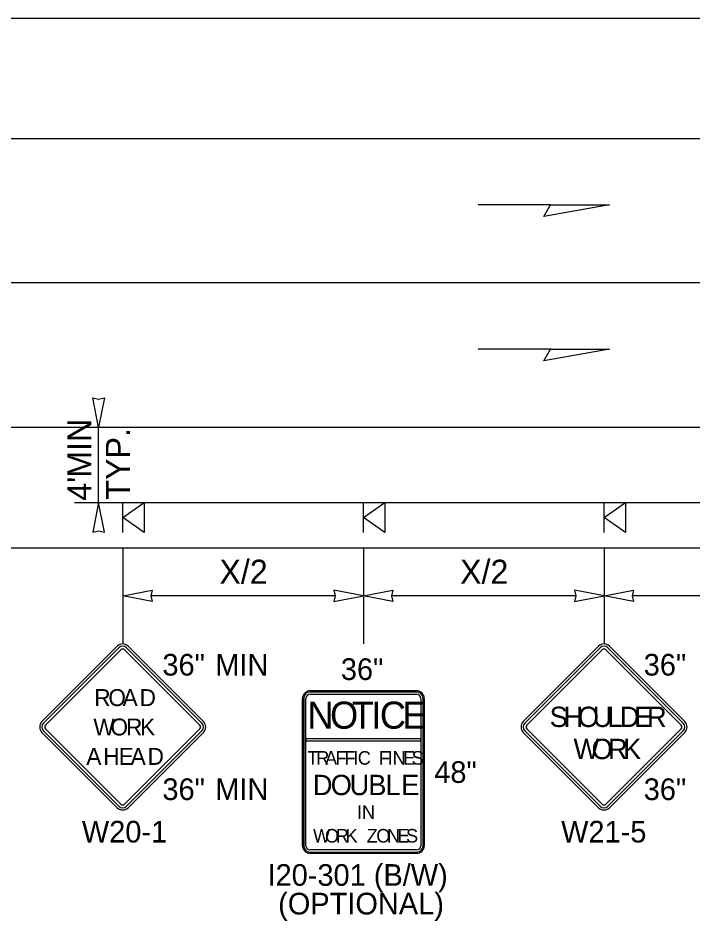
# Model space of a CAD drawing. Extents: x 99999.1 to 100055.7, y 99995 to 100010.7.
# Drawn here: x 100021.827 to 100024.071, y 100003.995 to 100006.996 of the extents above; entities that cross this region are included whole.
import ezdxf

# ---------------------------------------------------------------- set-up
doc = ezdxf.new("R2010")
doc.units = 0
for name, color, linetype in [('RD_ED_ShoulderPavedEdge', 7, 'Continuous'), ('RD_MK_LineEdgeWhite', 7, 'Continuous'), ('RD_MK_LineEdgeYellow', 7, 'Continuous'), ('RD_MK_LineLane', 7, 'Continuous'), ('TR_SN_ConstructionSigns', 7, 'Continuous'), ('TR_WZ_PortableSignMountBlk-Org', 7, 'Continuous'), ('TR_WZ_PortableSignMountBlk-Wht', 7, 'Continuous'), ('TR_WZ_WorkZoneDetails', 7, 'Continuous'), ('TR_WZ_WorkZoneTextCurrent', 7, 'Continuous')]:
    doc.layers.add(name, color=color, linetype=linetype)

msp = doc.modelspace()

# ---------------------------------------------------------------- linework, layer by layer
at = {"layer": 'RD_ED_ShoulderPavedEdge'}
for p, q in [((100020.8283, 100006.9957), (100035.62, 100006.9957)), ((100020.8283, 100005.2357), (100035.62, 100005.2357))]:
    msp.add_line(p, q, dxfattribs=at)
at = {"layer": 'RD_MK_LineEdgeWhite'}
msp.add_line((100020.8283, 100005.6357), (100035.62, 100005.6357), dxfattribs=at)
at = {"layer": 'RD_MK_LineEdgeYellow'}
msp.add_line((100020.8283, 100006.5957), (100035.62, 100006.5957), dxfattribs=at)
at = {"layer": 'RD_MK_LineLane'}
msp.add_lwpolyline([(100035.62, 100006.1157), (100020.8283, 100006.1157)], dxfattribs=at)
at = {"layer": 'TR_SN_ConstructionSigns'}
for p, q in [((100022.1574, 100004.9083), (100021.9068, 100004.6577)), ((100022.1624, 100004.9033), (100021.9118, 100004.6528)), ((100021.9187, 100004.6458), (100022.1693, 100004.8964)), ((100022.1812, 100004.8964), (100022.4318, 100004.6458)), ((100022.4388, 100004.6528), (100022.1882, 100004.9033)), ((100022.4438, 100004.6577), (100022.1932, 100004.9083)), ((100023.7574, 100004.9083), (100023.5068, 100004.6577)), ((100023.7624, 100004.9033), (100023.5118, 100004.6528)), ((100023.5187, 100004.6458), (100023.7693, 100004.8964)), ((100023.7812, 100004.8964), (100024.0318, 100004.6458)), ((100024.0388, 100004.6528), (100023.7882, 100004.9033)), ((100024.0438, 100004.6577), (100023.7932, 100004.9083)), ((100022.7981, 100004.76), (100023.1525, 100004.76)), ((100023.1525, 100004.76), (100022.7981, 100004.76)), ((100023.1525, 100004.76), (100022.7981, 100004.76)), ((100022.7728, 100004.2453), (100022.7728, 100004.7347)), ((100022.7728, 100004.7347), (100022.7728, 100004.2453)), ((100022.7728, 100004.7347), (100022.7728, 100004.2453)), ((100022.777, 100004.7347), (100022.777, 100004.2453)), ((100022.784, 100004.6004), (100022.784, 100004.7347)), ((100023.1525, 100004.7558), (100022.7981, 100004.7558)), ((100022.7981, 100004.7488), (100023.1525, 100004.7488)), ((100023.1665, 100004.7347), (100023.1665, 100004.6004)), ((100023.1736, 100004.2453), (100023.1736, 100004.7347)), ((100023.1778, 100004.7347), (100023.1778, 100004.2453)), ((100023.1778, 100004.2453), (100023.1778, 100004.7347)), ((100023.1778, 100004.2453), (100023.1778, 100004.7347)), ((100021.9068, 100004.6219), (100022.1574, 100004.3714)), ((100021.9118, 100004.6269), (100022.1624, 100004.3763)), ((100022.1693, 100004.3833), (100021.9187, 100004.6339)), ((100022.4318, 100004.6339), (100022.1812, 100004.3833)), ((100022.1882, 100004.3763), (100022.4388, 100004.6269)), ((100022.1932, 100004.3714), (100022.4438, 100004.6219)), ((100023.5068, 100004.6219), (100023.7574, 100004.3714)), ((100023.5118, 100004.6269), (100023.7624, 100004.3763)), ((100023.7693, 100004.3833), (100023.5187, 100004.6339)), ((100024.0318, 100004.6339), (100023.7812, 100004.3833)), ((100023.7882, 100004.3763), (100024.0388, 100004.6269)), ((100023.7932, 100004.3714), (100024.0438, 100004.6219)), ((100022.784, 100004.6004), (100022.784, 100004.6004)), ((100023.1665, 100004.6004), (100022.784, 100004.6004)), ((100022.784, 100004.6004), (100022.784, 100004.5934)), ((100022.784, 100004.5934), (100022.784, 100004.6004)), ((100022.784, 100004.5934), (100023.1665, 100004.5934)), ((100022.784, 100004.2453), (100022.784, 100004.5934)), ((100023.1665, 100004.5934), (100023.1665, 100004.6004)), ((100023.1665, 100004.6004), (100023.1665, 100004.5934)), ((100023.1665, 100004.5934), (100023.1665, 100004.2453)), ((100023.1525, 100004.2313), (100022.7981, 100004.2313)), ((100022.7981, 100004.2242), (100023.1525, 100004.2242)), ((100023.1525, 100004.22), (100022.7981, 100004.22)), ((100022.7981, 100004.22), (100023.1525, 100004.22)), ((100022.7981, 100004.22), (100023.1525, 100004.22))]:
    msp.add_line(p, q, dxfattribs=at)
for centre, radius, start, end in [((100022.1753, 100004.8904), 0.0253, 45, 135), ((100022.1753, 100004.8904), 0.0183, 45, 135), ((100023.7753, 100004.8904), 0.0253, 45, 135), ((100023.7753, 100004.8904), 0.0183, 45, 135), ((100022.1753, 100004.8904), 0.00844, 45, 135), ((100023.7753, 100004.8904), 0.00844, 45, 135), ((100022.7981, 100004.7347), 0.0253, 90, 180), ((100022.7981, 100004.7347), 0.0253, 90, 180), ((100022.7981, 100004.7347), 0.0253, 90, 180), ((100023.1525, 100004.7347), 0.0253, 0, 90), ((100023.1525, 100004.7347), 0.0253, 0, 90), ((100023.1525, 100004.7347), 0.0253, 0, 90), ((100022.7981, 100004.7347), 0.0211, 90, 180), ((100022.7981, 100004.7347), 0.0141, 90, 180), ((100023.1525, 100004.7347), 0.0211, 0, 90), ((100023.1525, 100004.7347), 0.0141, 0, 90), ((100021.9247, 100004.6398), 0.0253, 135, 225), ((100021.9247, 100004.6398), 0.0183, 135, 225), ((100021.9247, 100004.6398), 0.00844, 135, 225), ((100022.4259, 100004.6398), 0.00844, 315, 45), ((100022.4259, 100004.6398), 0.0183, 315, 45), ((100022.4259, 100004.6398), 0.0253, 315, 45), ((100023.5247, 100004.6398), 0.0253, 135, 225), ((100023.5247, 100004.6398), 0.0183, 135, 225), ((100023.5247, 100004.6398), 0.00844, 135, 225), ((100024.0259, 100004.6398), 0.00844, 315, 45), ((100024.0259, 100004.6398), 0.0183, 315, 45), ((100024.0259, 100004.6398), 0.0253, 315, 45), ((100022.1753, 100004.3893), 0.0253, 225, 315), ((100022.1753, 100004.3893), 0.0183, 225, 315), ((100022.1753, 100004.3893), 0.00844, 225, 315), ((100023.7753, 100004.3893), 0.0253, 225, 315), ((100023.7753, 100004.3893), 0.0183, 225, 315), ((100023.7753, 100004.3893), 0.00844, 225, 315), ((100022.7981, 100004.2453), 0.0253, 180, 270), ((100022.7981, 100004.2453), 0.0253, 180, 270), ((100022.7981, 100004.2453), 0.0253, 180, 270), ((100022.7981, 100004.2453), 0.0211, 180, 270), ((100022.7981, 100004.2453), 0.0141, 180, 270), ((100023.1525, 100004.2453), 0.0253, 270, 0), ((100023.1525, 100004.2453), 0.0253, 270, 0), ((100023.1525, 100004.2453), 0.0211, 270, 0), ((100023.1525, 100004.2453), 0.0141, 270, 0), ((100023.1525, 100004.2453), 0.0253, 270, 0)]:
    msp.add_arc(centre, radius, start, end, dxfattribs=at)
at = {"layer": 'TR_WZ_PortableSignMountBlk-Org'}
for p, q in [((100022.1753, 100005.2858), (100022.1753, 100005.3858)), ((100023.7753, 100005.2858), (100023.7753, 100005.3858))]:
    msp.add_line(p, q, dxfattribs=at)
for points in [[(100022.1753, 100005.3357), (100022.2471, 100005.3858), (100022.2471, 100005.2858)], [(100023.7753, 100005.3357), (100023.8471, 100005.3858), (100023.8471, 100005.2858)]]:
    msp.add_lwpolyline(points, close=True, dxfattribs=at)
at = {"layer": 'TR_WZ_PortableSignMountBlk-Wht'}
msp.add_line((100022.9753, 100005.2857), (100022.9753, 100005.3857), dxfattribs=at)
msp.add_lwpolyline([(100022.9753, 100005.3356), (100023.0471, 100005.3857), (100023.0471, 100005.2857)], close=True, dxfattribs=at)
at = {"layer": 'TR_WZ_WorkZoneDetails'}
for p, q in [((100023.5976, 100006.375), (100023.3565, 100006.375)), ((100023.5976, 100005.895), (100023.3565, 100005.895)), ((100022.0153, 100005.6357), (100022.1753, 100005.6357)), ((100022.0953, 100005.3858), (100022.0953, 100005.6357)), ((100022.0153, 100005.3858), (100022.1753, 100005.3858)), ((100022.1753, 100005.3858), (100026.6368, 100005.3858)), ((100022.1753, 100005.2357), (100022.1753, 100004.9157)), ((100022.9753, 100005.236), (100022.9753, 100004.9157)), ((100023.7753, 100005.236), (100023.7753, 100004.9157)), ((100022.8815, 100005.0757), (100022.269, 100005.0757)), ((100023.6815, 100005.0757), (100023.069, 100005.0757)), ((100024.6815, 100005.0757), (100023.869, 100005.0757))]:
    msp.add_line(p, q, dxfattribs=at)
for points in [[(100023.7941, 100006.375), (100023.5753, 100006.3364), (100023.5976, 100006.375)], [(100023.7941, 100005.895), (100023.5753, 100005.8564), (100023.5976, 100005.895)], [(100022.0953, 100005.6357), (100022.076, 100005.734), (100022.0953, 100005.7295), (100022.1146, 100005.734)], [(100022.0953, 100005.3858), (100022.076, 100005.2875), (100022.0953, 100005.2921), (100022.1146, 100005.2875)], [(100022.1753, 100005.0757), (100022.2736, 100005.095), (100022.269, 100005.0757), (100022.2736, 100005.0565)], [(100022.9753, 100005.0757), (100022.877, 100005.095), (100022.8815, 100005.0757), (100022.877, 100005.0565)], [(100022.9753, 100005.0757), (100023.0736, 100005.095), (100023.069, 100005.0757), (100023.0736, 100005.0565)], [(100023.7753, 100005.0757), (100023.677, 100005.095), (100023.6815, 100005.0757), (100023.677, 100005.0565)], [(100023.7753, 100005.0757), (100023.8736, 100005.095), (100023.869, 100005.0757), (100023.8736, 100005.0565)]]:
    msp.add_lwpolyline(points, close=True, dxfattribs=at)

# ---------------------------------------------------------------- texts
at = {"layer": 'TR_SN_ConstructionSigns'}
for s, p in [('36"', (100022.3073, 100004.8107)), ('MIN', (100022.4829, 100004.8107)), ('36"', (100023.9073, 100004.8107)), ('36"', (100022.9005, 100004.796)), ('48"', (100023.211, 100004.454)), ('36"', (100022.3073, 100004.397)), ('MIN', (100022.4829, 100004.397)), ('36"', (100023.9073, 100004.397)), ('W20-1', (100022.0395, 100004.2559)), ('W21-5', (100023.6327, 100004.2559)), ('I20-301 (B/W)', (100022.6567, 100004.112)), ('(OPTIONAL)', (100022.6921, 100004.0169))]:
    msp.add_text(s, height=0.072, rotation=360, dxfattribs=at).set_placement(p)
for s, height, p in [('R', 0.0562, (100022.0807, 100004.7094)), ('O', 0.0562, (100022.1276, 100004.7094)), ('A', 0.0562, (100022.1751, 100004.7094)), ('D', 0.0562, (100022.2316, 100004.7094)), ('N', 0.09, (100022.7895, 100004.6342)), ('O', 0.09, (100022.8646, 100004.6342)), ('T', 0.09, (100022.9367, 100004.6342)), ('I', 0.09, (100023.0019, 100004.6342)), ('C', 0.09, (100023.0302, 100004.6342)), ('E', 0.09, (100023.1052, 100004.6342)), ('S', 0.0675, (100023.5946, 100004.6398)), ('H', 0.0675, (100023.6407, 100004.6398)), ('O', 0.0675, (100023.6883, 100004.6398)), ('U', 0.0675, (100023.7379, 100004.6398)), ('L', 0.0675, (100023.7865, 100004.6398)), ('D', 0.0675, (100023.8278, 100004.6398)), ('E', 0.0675, (100023.8754, 100004.6398)), ('R', 0.0675, (100023.9182, 100004.6398)), ('O', 0.0562, (100022.1347, 100004.6117)), ('W', 0.0562, (100022.0778, 100004.6117)), ('R', 0.0562, (100022.1862, 100004.6117)), ('K', 0.0562, (100022.2334, 100004.6117)), ('W', 0.0675, (100023.674, 100004.533)), ('O', 0.0675, (100023.7341, 100004.533)), ('R', 0.0675, (100023.7885, 100004.533)), ('K', 0.0675, (100023.8387, 100004.533)), ('A', 0.0562, (100022.0543, 100004.514)), ('H', 0.0562, (100022.1106, 100004.514)), ('E', 0.0562, (100022.1623, 100004.514)), ('A', 0.0562, (100022.2017, 100004.514)), ('D', 0.0562, (100022.258, 100004.514)), ('T', 0.045, (100022.7894, 100004.5146)), ('R', 0.045, (100022.8187, 100004.5146)), ('A', 0.045, (100022.8479, 100004.5146)), ('F', 0.045, (100022.883, 100004.5146)), ('F', 0.045, (100022.9123, 100004.5146)), ('I', 0.045, (100022.9415, 100004.5146)), ('C', 0.045, (100022.9568, 100004.5146)), ('F', 0.045, (100023.027, 100004.5146)), ('I', 0.045, (100023.0563, 100004.5146)), ('N', 0.045, (100023.0725, 100004.5146)), ('E', 0.045, (100023.1076, 100004.5146)), ('S', 0.045, (100023.1359, 100004.5146)), ('D', 0.0675, (100022.8075, 100004.4134)), ('O', 0.0675, (100022.8669, 100004.4134)), ('U', 0.0675, (100022.9297, 100004.4134)), ('B', 0.0675, (100022.9918, 100004.4134)), ('L', 0.0675, (100023.0492, 100004.4134)), ('E', 0.0675, (100023.1012, 100004.4134)), ('I', 0.045, (100022.9546, 100004.3346)), ('N', 0.045, (100022.9708, 100004.3346)), ('W', 0.045, (100022.8081, 100004.2559)), ('O', 0.045, (100022.8477, 100004.2559)), ('R', 0.045, (100022.8833, 100004.2559)), ('K', 0.045, (100022.9161, 100004.2559)), ('Z', 0.045, (100022.9863, 100004.2559)), ('O', 0.045, (100023.0183, 100004.2559)), ('N', 0.045, (100023.0538, 100004.2559)), ('E', 0.045, (100023.0889, 100004.2559)), ('S', 0.045, (100023.1173, 100004.2559))]:
    msp.add_text(s, height=height, dxfattribs=at).set_placement(p)
at = {"layer": 'TR_WZ_WorkZoneTextCurrent'}
for s, rotation, p in [('MIN', 90, (100022.0713, 100005.4682)), ('TYP.', 90, (100022.1993, 100005.3954)), ("4'", 90, (100022.0713, 100005.3917)), ('X/2', 360, (100022.4968, 100005.1157)), ('X/2', 360, (100023.2968, 100005.1157))]:
    msp.add_text(s, height=0.08, rotation=rotation, dxfattribs=at).set_placement(p)

doc.saveas('drawing.dxf')
